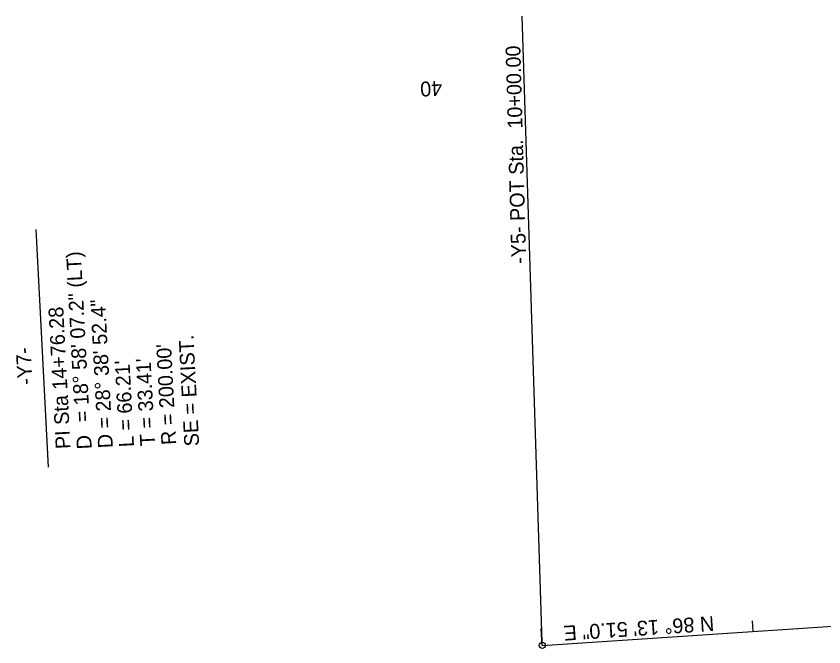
# Model space of a CAD drawing. Extents: x 2367848 to 2369479, y 800728 to 808616.
# Drawn here: x 2368316.2 to 2368698.2, y 804048.8 to 804347.2 of the extents above; entities that cross this region are included whole.
import ezdxf

# ---------------------------------------------------------------- set-up
doc = ezdxf.new("R2010")
doc.units = 0
for name, color, linetype in [('Prop Horizontal Alignment', 7, 'Continuous'), ('Prop Horizontal Alignment Curve and Spiral Data', 7, 'Continuous'), ('Prop Horizontal Alignment Direction Label', 7, 'Continuous'), ('Prop Horizontal Alignment Station Label', 7, 'Continuous'), ('Prop Horizontal Alignment Tick Label', 7, 'Continuous'), ('Prop Horizontal Alignment Tick Large', 7, 'Continuous'), ('Prop Horizontal Alignment Tick Small', 7, 'Continuous')]:
    doc.layers.add(name, color=color, linetype=linetype)

msp = doc.modelspace()

# ---------------------------------------------------------------- linework, layer by layer
at = {"layer": 'Prop Horizontal Alignment'}
msp.add_line((2368565.04, 804049.45), (2368822.8, 804066.43), dxfattribs=at)
at = {"layer": 'Prop Horizontal Alignment Station Label'}
for p, q in [((2368564.94, 804050.94), (2368555.46, 804347.17)), ((2368331.58, 804133.78), (2368325.7, 804246.21))]:
    msp.add_line(p, q, dxfattribs=at)
msp.add_circle((2368565.04, 804049.45), 1.5, dxfattribs=at)
at = {"layer": 'Prop Horizontal Alignment Tick Large'}
msp.add_line((2368565.04, 804049.45), (2368564.51, 804057.43), dxfattribs=at)
at = {"layer": 'Prop Horizontal Alignment Tick Small'}
msp.add_line((2368664.82, 804056.02), (2368664.49, 804061.01), dxfattribs=at)

# ---------------------------------------------------------------- texts
at = {"layer": 'Prop Horizontal Alignment Curve and Spiral Data'}
for s, rotation, p in [('= 18%%d 58\' 07.2" (LT)', 92.9979, (2368351.05, 804155.21)), ('D = 28%%d 38\' 52.4"', 92.9979, (2368362, 804142.92)), ('PI Sta 14+76.28', 92.9979, (2368341.99, 804142.55)), ('SE = EXIST.', 92.9979, (2368402.81, 804143.84)), ("R = 200.00'", 92.9979, (2368391.96, 804144.49)), ('-Y7-', 93.2444, (2368324.03, 804172.95)), ("T = 33.41'", 92.9979, (2368381.97, 804143.96)), ("L = 66.21'", 92.9979, (2368371.98, 804143.44)), ('D', 92.9979, (2368352.01, 804142.4))]:
    msp.add_text(s, height=7, rotation=rotation, dxfattribs=at).set_placement(p)
at = {"layer": 'Prop Horizontal Alignment Direction Label'}
msp.add_text('N 86%%d 13\' 51.0" E', height=7, rotation=183.7692, dxfattribs=at).set_placement((2368646.06, 804063.35))
at = {"layer": 'Prop Horizontal Alignment Station Label'}
msp.add_text('-Y5- POT Sta.  10+00.00', height=7, rotation=91.5651, dxfattribs=at).set_placement((2368557.46, 804230.09))
at = {"layer": 'Prop Horizontal Alignment Tick Label'}
msp.add_text('40', height=7, rotation=182.7965, dxfattribs=at).set_placement((2368517.53, 804316.58))

doc.saveas('drawing.dxf')
